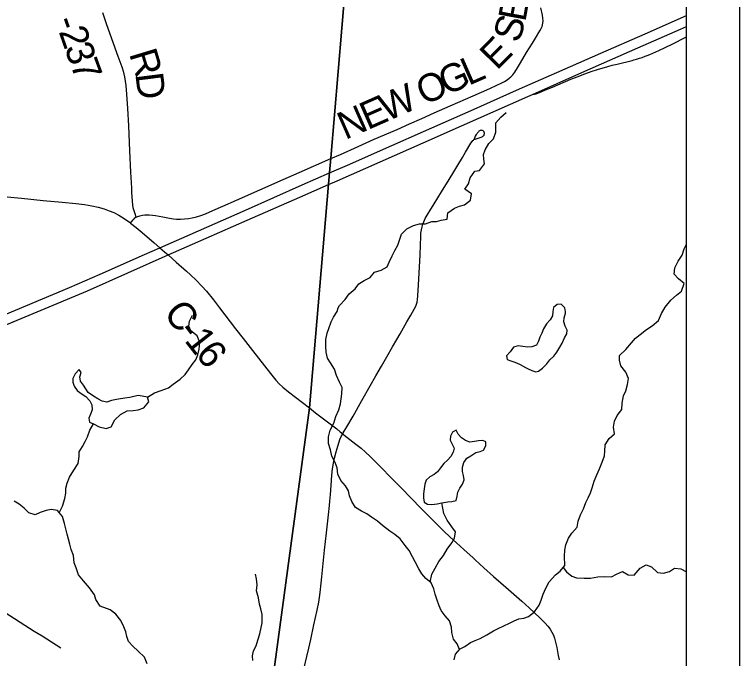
# Model space of a CAD drawing. Extents: x 0 to 34, y 0 to 22.
# Drawn here: x 7.686 to 9.17, y 16.336 to 17.655 of the extents above; entities that cross this region are included whole.
import ezdxf

# ---------------------------------------------------------------- set-up
doc = ezdxf.new("R2010")
doc.units = 0
for name, color, linetype in [('Default', 7, 'Continuous'), ('GM_X_County_Road', 7, 'Continuous'), ('GM_X_County_Road_Text', 7, 'Continuous'), ('GM_X_Interchange_Ramps', 7, 'Continuous'), ('GM_X_Interstate_Location', 7, 'Continuous'), ('GM_X_Interstate_Route', 7, 'Continuous'), ('GM_X_Minor_Lake', 7, 'Continuous'), ('GM_X_Minor_River', 7, 'Continuous'), ('GM_X_Township_Road', 7, 'Continuous'), ('GM_X_Township_Road_Text', 7, 'Continuous'), ('SH_Cut_Line', 7, 'Continuous'), ('SH_Data', 7, 'Continuous')]:
    doc.layers.add(name, color=color, linetype=linetype)

msp = doc.modelspace()

# ---------------------------------------------------------------- linework, layer by layer
at = {"layer": 'Default'}
msp.add_lwpolyline([(3.47, 19.2407), (3.2768, 17.1355), (3.2667, 16.919), (3.1974, 16.1596), (3.1343, 15.4291), (3.1796, 15.4266), (4.2078, 15.3826), (4.2393, 15.3805), (4.819, 15.349), (5.5157, 15.319), (7.9465, 15.1727), (8.1234, 15.1688), (8.137, 15.3372), (8.146, 15.4642), (8.2031, 16.209), (8.2895, 16.85), (8.3286, 17.3076), (8.3307, 17.3314), (8.3334, 17.361), (8.3935, 18.0719)], dxfattribs=at)
msp.add_lwpolyline([(8.4279, 13.6252), (9.0621, 13.6252), (9.0621, 18.0279), (9.0619, 18.0279), (8.9638, 18.036), (8.3935, 18.0719), (8.3334, 17.361), (8.3307, 17.3314), (8.3286, 17.3076), (8.2895, 16.85), (8.2031, 16.209), (8.146, 15.4642), (8.137, 15.3372), (8.1234, 15.1688), (8.3761, 15.1587), (8.4023, 15.1576), (8.4024, 15.1386)], close=True, dxfattribs=at)
at = {"layer": 'GM_X_County_Road'}
for points in [[(8.3337, 17.3604), (8.3531, 17.3688), (8.3893, 17.3851), (8.4223, 17.3996), (8.469, 17.42), (8.4945, 17.4314), (8.5195, 17.4425), (8.5451, 17.4538), (8.5781, 17.4683), (8.6253, 17.4889), (8.6589, 17.5036), (8.6736, 17.5102), (8.6826, 17.5145), (8.6891, 17.518), (8.6948, 17.5216), (8.6988, 17.5245), (8.702, 17.5273), (8.7062, 17.5318), (8.7102, 17.5372), (8.7158, 17.546), (8.7218, 17.5562), (8.7341, 17.5771), (8.7462, 17.5967), (8.7524, 17.6067), (8.7615, 17.6215), (8.7642, 17.6264), (8.7661, 17.6308), (8.7672, 17.6343), (8.7678, 17.6372), (8.7682, 17.642), (8.7679, 17.6475), (8.7667, 17.6541), (8.7637, 17.6688)], [(7.9348, 17.2401), (7.9382, 17.2416), (7.9425, 17.2429), (7.948, 17.2441), (7.9524, 17.2448), (7.9568, 17.245), (7.9612, 17.245), (7.9681, 17.2444), (7.9743, 17.2436), (7.9896, 17.2406), (8.003, 17.2381), (8.0115, 17.2368), (8.0177, 17.2363), (8.0257, 17.2362), (8.0337, 17.2366), (8.0417, 17.2374), (8.0496, 17.2389), (8.0585, 17.2411), (8.0674, 17.2438), (8.0767, 17.2472), (8.0916, 17.2535), (8.112, 17.2625), (8.1405, 17.275), (8.236, 17.317), (8.2683, 17.3316), (8.3337, 17.3604)], [(7.4691, 17.3047), (7.4709, 17.3039), (7.477, 17.3022), (7.4844, 17.3008), (7.4968, 17.2994), (7.5252, 17.2968), (7.5709, 17.2921), (7.5957, 17.2896), (7.6333, 17.2854), (7.7001, 17.2788), (7.7446, 17.2743), (7.783, 17.271), (7.8109, 17.2683), (7.8288, 17.266), (7.844, 17.2633), (7.8567, 17.2605), (7.8692, 17.257), (7.8797, 17.2533), (7.8888, 17.2495), (7.8991, 17.244), (7.9102, 17.2372), (7.9209, 17.2298), (7.9232, 17.2281)], [(7.9232, 17.2281), (7.9255, 17.2309), (7.9288, 17.2349), (7.9305, 17.2369), (7.9323, 17.2386), (7.9348, 17.2401)], [(7.9232, 17.2281), (7.9347, 17.2193), (7.9471, 17.2091), (7.9714, 17.1878), (7.9834, 17.1773), (7.9929, 17.169), (8, 17.1627), (8.0167, 17.148), (8.0377, 17.1296), (8.0461, 17.1222), (8.0577, 17.111), (8.0693, 17.099), (8.0788, 17.0884), (8.0929, 17.0711), (8.1052, 17.0547), (8.1385, 17.0113), (8.1538, 16.9918), (8.1729, 16.9673), (8.2099, 16.9197), (8.2206, 16.9066), (8.2278, 16.8989), (8.235, 16.892), (8.2471, 16.8822), (8.2897, 16.8494)], [(8.2897, 16.8494), (8.3023, 16.8398), (8.3456, 16.8064), (8.3527, 16.8006), (8.3579, 16.7965)], [(8.3579, 16.7965), (8.3603, 16.7947), (8.3848, 16.7754), (8.3954, 16.7668), (8.4044, 16.7592), (8.414, 16.7502), (8.4285, 16.7358), (8.4647, 16.6991), (8.4795, 16.6839), (8.4958, 16.6669), (8.5207, 16.6417), (8.5473, 16.6148), (8.565, 16.5973), (8.5772, 16.5858), (8.5909, 16.5732), (8.606, 16.5593), (8.6248, 16.5422), (8.6294, 16.5381), (8.6468, 16.5222), (8.6668, 16.5045), (8.692, 16.4824), (8.7247, 16.4537), (8.7395, 16.4404), (8.7618, 16.4196), (8.7723, 16.4089), (8.7776, 16.4028), (8.7825, 16.3963), (8.7861, 16.3904), (8.7892, 16.3842), (8.7917, 16.3778), (8.7939, 16.3699), (8.796, 16.3589), (8.799, 16.3425), (8.8012, 16.3335)]]:
    msp.add_lwpolyline(points, dxfattribs=at)
at = {"layer": 'GM_X_Interchange_Ramps'}
msp.add_lwpolyline([(8.7465, 17.4913), (8.7508, 17.4918), (8.7539, 17.4927), (8.7574, 17.494), (8.7639, 17.4966), (8.7734, 17.5007), (8.7872, 17.5062), (8.8247, 17.5226), (8.8381, 17.5279), (8.8537, 17.5338), (8.8668, 17.5383), (8.8798, 17.5427), (8.9007, 17.5489), (8.9099, 17.5513), (8.9199, 17.5538), (8.9503, 17.5612), (8.9543, 17.5622), (8.9597, 17.5637), (8.9653, 17.5655), (8.9712, 17.5675), (8.9769, 17.5697), (8.9813, 17.5713), (8.9868, 17.5736), (9.0051, 17.5818), (9.0328, 17.5943), (9.0608, 17.6088), (9.0621, 17.6095)], dxfattribs=at)
at = {"layer": 'GM_X_Interstate_Route'}
for points in [[(7.6525, 17.0355), (7.7984, 17.0958), (7.8609, 17.1234), (7.952, 17.1634), (7.9834, 17.1773), (8.1588, 17.2547), (8.2747, 17.3062), (8.331, 17.3309), (8.3675, 17.3468), (8.4583, 17.3872), (8.5231, 17.4157), (8.6209, 17.4589), (8.7197, 17.5027), (8.796, 17.5363), (8.8864, 17.5759), (8.9769, 17.6157), (9.0621, 17.6533)], [(8.7465, 17.4913), (8.8475, 17.5363), (8.9625, 17.5867), (9.0494, 17.6251), (9.0621, 17.6308)], [(6.6115, 16.581), (6.7509, 16.6383), (6.8821, 16.6934), (6.9924, 16.7387), (7.2374, 16.8408), (7.3137, 16.8725), (7.3391, 16.883), (7.3498, 16.8874), (7.436, 16.9231), (7.5336, 16.9635), (7.8352, 17.0892), (8, 17.1627), (8.0503, 17.1852), (8.162, 17.2337), (8.2701, 17.2811), (8.3288, 17.307), (8.3462, 17.3149), (8.5226, 17.3923), (8.6009, 17.4272), (8.7368, 17.4871), (8.7465, 17.4913)]]:
    msp.add_lwpolyline(points, dxfattribs=at)
at = {"layer": 'GM_X_Minor_Lake'}
for points in [[(8.8138, 17.0435), (8.8139, 17.0463), (8.8129, 17.0543), (8.8051, 17.062), (8.7971, 17.0611), (8.7895, 17.0555), (8.7881, 17.0468), (8.7876, 17.0381), (8.7825, 17.0299), (8.7751, 17.0217), (8.7692, 17.0115), (8.7653, 17.0029), (8.7613, 16.9946), (8.7589, 16.9863), (8.7545, 16.9781), (8.7454, 16.9748), (8.737, 16.9739), (8.7268, 16.9752), (8.7174, 16.9765), (8.7075, 16.9741), (8.7005, 16.9647), (8.6931, 16.9565), (8.6944, 16.9485), (8.7023, 16.9457), (8.7106, 16.9429), (8.7196, 16.9393), (8.7286, 16.9342), (8.7293, 16.9339)], [(8.7293, 16.9339), (8.7376, 16.9298), (8.7451, 16.9259), (8.7534, 16.9231), (8.7591, 16.9249), (8.7672, 16.9308), (8.7757, 16.9401), (8.7823, 16.9483), (8.7904, 16.9557), (8.7963, 16.964), (8.8022, 16.9741), (8.8073, 16.9823), (8.8117, 16.9929), (8.8168, 17.0011), (8.8177, 17.0087), (8.8133, 17.0167), (8.8104, 17.0255), (8.8114, 17.0342), (8.8138, 17.0435)], [(7.9073, 16.8687), (7.9029, 16.8678), (7.8942, 16.8669), (7.8843, 16.8644), (7.8744, 16.8612), (7.8653, 16.8636), (7.8563, 16.8684), (7.8473, 16.8735), (7.8365, 16.8809), (7.8317, 16.8886), (7.8266, 16.8963), (7.8211, 16.9043), (7.8197, 16.9131), (7.8218, 16.9222), (7.8181, 16.9279), (7.8096, 16.919), (7.8049, 16.91), (7.8051, 16.902), (7.8076, 16.8944), (7.8142, 16.8851), (7.8224, 16.8793), (7.8318, 16.8727), (7.8396, 16.8638), (7.8443, 16.8557), (7.8445, 16.8458), (7.8413, 16.8368), (7.8381, 16.8285), (7.8394, 16.8201), (7.8477, 16.8169)], [(7.8477, 16.8169), (7.8593, 16.8106), (7.8736, 16.8077), (7.8835, 16.8109), (7.8914, 16.8248), (7.903, 16.836), (7.9164, 16.8433), (7.9289, 16.8442), (7.9392, 16.8455), (7.9506, 16.8498), (7.9604, 16.8621), (7.9583, 16.8717)], [(7.9583, 16.8717), (7.9394, 16.8747), (7.9299, 16.873), (7.9215, 16.8709), (7.9113, 16.8696), (7.9073, 16.8687)], [(8.6092, 16.7425), (8.6123, 16.7468), (8.6199, 16.7516), (8.6303, 16.7582), (8.6394, 16.7603), (8.6459, 16.7632), (8.651, 16.7718), (8.6512, 16.7798), (8.6445, 16.783), (8.6361, 16.782), (8.6277, 16.7807), (8.6182, 16.7797), (8.6092, 16.7825), (8.6014, 16.7884), (8.5943, 16.7957), (8.5899, 16.8038), (8.5823, 16.8001), (8.5783, 16.7915), (8.5782, 16.7832), (8.5818, 16.7751), (8.5858, 16.7671), (8.5841, 16.7591), (8.5794, 16.7501), (8.5724, 16.7427), (8.5651, 16.7356), (8.5581, 16.7266), (8.5518, 16.7184), (8.5449, 16.7129)], [(8.5449, 16.7129), (8.5361, 16.7085), (8.5288, 16.7018), (8.5263, 16.6931), (8.5246, 16.6837), (8.5233, 16.6738), (8.5231, 16.6655), (8.5244, 16.6567), (8.5315, 16.6521), (8.5406, 16.6519), (8.5509, 16.6532), (8.5611, 16.6553), (8.5733, 16.6569), (8.5816, 16.6579), (8.59, 16.6596), (8.5925, 16.6687), (8.5938, 16.677), (8.5974, 16.6853), (8.6028, 16.6935), (8.6068, 16.7022), (8.6051, 16.7113), (8.603, 16.7193), (8.6028, 16.728), (8.6056, 16.7375), (8.6092, 16.7425)]]:
    msp.add_lwpolyline(points, dxfattribs=at)
at = {"layer": 'GM_X_Minor_River'}
for points in [[(8.3487, 17.0548), (8.3511, 17.0591), (8.3627, 17.0718), (8.3713, 17.0834), (8.3832, 17.0934), (8.3907, 17.1039), (8.4014, 17.1102), (8.4141, 17.1168), (8.423, 17.1276), (8.4364, 17.1319), (8.4487, 17.1385), (8.4527, 17.1483), (8.459, 17.161), (8.4645, 17.1719), (8.4708, 17.1828), (8.4749, 17.1949), (8.4781, 17.2051), (8.489, 17.2163), (8.5028, 17.2228), (8.515, 17.2264), (8.5275, 17.2265), (8.5401, 17.2312), (8.5496, 17.2314), (8.5592, 17.2339), (8.5714, 17.2363), (8.5731, 17.2488), (8.587, 17.2584), (8.5973, 17.2627), (8.6069, 17.2656), (8.6196, 17.2748), (8.6214, 17.2881), (8.6079, 17.2974), (8.6157, 17.3083), (8.6186, 17.3208), (8.6284, 17.3346), (8.6379, 17.336), (8.648, 17.3494), (8.6471, 17.3589), (8.6458, 17.3685), (8.6494, 17.3783), (8.6568, 17.391), (8.6665, 17.4007), (8.6713, 17.4143), (8.6712, 17.4238), (8.6713, 17.4333), (8.6814, 17.4448), (8.6923, 17.4545)], [(9.0106, 17.043), (9.0184, 17.0561), (9.0301, 17.0703), (9.0417, 17.0807), (9.0518, 17.0889), (9.057, 17.104), (9.0454, 17.1137), (9.0369, 17.1237), (9.0379, 17.1366), (9.045, 17.1498), (9.0528, 17.1625), (9.0573, 17.1753), (9.0621, 17.1846)], [(8.5967, 16.3547), (8.5923, 16.3663), (8.585, 16.376), (8.5811, 16.3897), (8.5809, 16.4003), (8.5766, 16.4133), (8.5678, 16.4237), (8.5593, 16.4345), (8.5553, 16.4441), (8.5506, 16.4578), (8.5474, 16.4681), (8.5446, 16.4788), (8.5388, 16.4911), (8.5277, 16.5004), (8.5199, 16.51), (8.5137, 16.52), (8.506, 16.5342), (8.5005, 16.5446), (8.494, 16.5572), (8.4858, 16.5676), (8.4755, 16.5811), (8.4647, 16.5904), (8.4543, 16.5974), (8.439, 16.6087), (8.4289, 16.6173), (8.417, 16.6259), (8.4072, 16.6325), (8.3964, 16.6384), (8.384, 16.6455), (8.3763, 16.6578), (8.372, 16.6692), (8.3696, 16.6799), (8.3633, 16.6899), (8.3541, 16.7007), (8.3479, 16.7141), (8.3463, 16.7267), (8.3423, 16.7377), (8.3354, 16.7508), (8.3326, 16.7634), (8.3284, 16.7767), (8.3286, 16.79), (8.3323, 16.8039), (8.3395, 16.8186), (8.3439, 16.8322), (8.3499, 16.8453), (8.3535, 16.8578), (8.3562, 16.8782), (8.3565, 16.8911), (8.351, 16.9022), (8.3449, 16.916), (8.3413, 16.929), (8.3325, 16.9417), (8.3263, 16.9513), (8.3239, 16.9638), (8.323, 16.9752), (8.3233, 16.9896), (8.3258, 17.0025), (8.3294, 17.0123), (8.3342, 17.0258), (8.339, 17.0356), (8.3464, 17.0472), (8.3487, 17.0548)], [(7.7774, 16.6349), (7.7836, 16.6486), (7.7888, 16.6637), (7.7906, 16.6747), (7.7904, 16.6849), (7.7933, 16.6955), (7.7981, 16.7075), (7.8071, 16.7222), (7.8157, 16.736), (7.8179, 16.75), (7.8181, 16.7599), (7.8248, 16.7704), (7.8303, 16.7805), (7.835, 16.7906), (7.8402, 16.8042), (7.8477, 16.8169), (7.8593, 16.8106), (7.8736, 16.8077), (7.8835, 16.8109), (7.8914, 16.8248), (7.903, 16.836), (7.9164, 16.8433), (7.9289, 16.8442), (7.9392, 16.8455), (7.9506, 16.8498), (7.9604, 16.8621), (7.9583, 16.8717), (7.9721, 16.8801), (7.9862, 16.8855), (8.0007, 16.8906), (8.0107, 16.8983), (8.0246, 16.9083), (8.0354, 16.9179), (8.042, 16.9277), (8.0498, 16.9385), (8.0572, 16.9482), (8.0612, 16.958), (8.0641, 16.9701), (8.0652, 16.9837), (8.0597, 16.9971), (8.0467, 17.0076), (8.0427, 17.0172), (8.0441, 17.027), (8.0504, 17.0394)], [(8.8127, 16.5266), (8.8123, 16.5456), (8.8126, 16.5585), (8.8147, 16.5691), (8.8203, 16.5826), (8.8273, 16.5927), (8.8382, 16.6054), (8.84, 16.6179), (8.8448, 16.6307), (8.8511, 16.6427), (8.8555, 16.6555), (8.8606, 16.6653), (8.865, 16.6754), (8.8686, 16.686), (8.8727, 16.6992), (8.8783, 16.7127), (8.8838, 16.7248), (8.8894, 16.7383), (8.8938, 16.7515), (8.8948, 16.7613), (8.8954, 16.7738), (8.9037, 16.7866), (8.9141, 16.7966), (8.9125, 16.8099), (8.9142, 16.8224), (8.9202, 16.8341), (8.9291, 16.8464), (8.9298, 16.8593), (8.9331, 16.8744), (8.9375, 16.8842), (8.9412, 16.8977), (8.9433, 16.9095), (8.9375, 16.9229), (8.9272, 16.936), (8.9244, 16.9474), (8.9246, 16.9569), (8.9373, 16.9691), (8.9493, 16.9826), (8.9571, 16.9923), (8.9668, 17), (8.9802, 17.01), (8.9914, 17.0174), (9.0045, 17.0285), (9.0106, 17.043)], [(7.9573, 16.3254), (7.9519, 16.3388), (7.9389, 16.3516), (7.9277, 16.3616), (7.9192, 16.3713), (7.9156, 16.3812), (7.9136, 16.3908), (7.9092, 16.4015), (7.9031, 16.4141), (7.8931, 16.4272), (7.8812, 16.4358), (7.8609, 16.4438), (7.8524, 16.4572), (7.8492, 16.4668), (7.8389, 16.481), (7.8267, 16.4957), (7.8167, 16.508), (7.8121, 16.5221), (7.8081, 16.5321), (7.8062, 16.5473), (7.8015, 16.5599), (7.7987, 16.5706), (7.7962, 16.5805), (7.7938, 16.5908), (7.791, 16.6018), (7.7878, 16.6129), (7.7836, 16.627), (7.774, 16.6393), (7.7604, 16.6415), (7.7508, 16.6394), (7.7379, 16.6351), (7.7276, 16.6308), (7.7148, 16.6344), (7.7051, 16.6441), (7.6954, 16.6527), (7.6846, 16.6589)], [(8.5371, 16.4925), (8.5403, 16.5089), (8.5474, 16.5216), (8.5549, 16.5351), (8.5642, 16.5475), (8.5717, 16.5602), (8.581, 16.5733), (8.5869, 16.5831), (8.5887, 16.5959), (8.5813, 16.6059), (8.5714, 16.6194), (8.5652, 16.6336), (8.5611, 16.6553)], [(8.586, 16.3338), (8.5889, 16.3455), (8.5982, 16.3564), (8.6081, 16.3611), (8.6197, 16.3692), (8.6292, 16.3732), (8.6395, 16.3775), (8.653, 16.3849), (8.6664, 16.3929), (8.6759, 16.3977), (8.6878, 16.4035), (8.6993, 16.409), (8.7088, 16.4133), (8.7188, 16.4173), (8.7287, 16.419), (8.7382, 16.4226), (8.7505, 16.4322), (8.7603, 16.4457), (8.7643, 16.4555), (8.7683, 16.4683), (8.7739, 16.4803), (8.7806, 16.4935), (8.7937, 16.5076), (8.8034, 16.515), (8.8127, 16.5266)], [(8.8095, 16.5226), (8.8158, 16.5137), (8.827, 16.5047), (8.8368, 16.5015), (8.852, 16.5008), (8.8656, 16.5009), (8.8804, 16.5033), (8.8948, 16.5045), (8.9081, 16.5039), (8.9184, 16.5094), (8.9307, 16.5148), (8.9426, 16.5077), (8.9547, 16.5071), (8.9672, 16.5213), (8.979, 16.5283), (8.9899, 16.5239), (9.0022, 16.5126), (9.0147, 16.5112), (9.0269, 16.5148), (9.0372, 16.5214), (9.0505, 16.52), (9.0621, 16.5138)], [(8.1738, 16.3321), (8.1728, 16.3416), (8.1753, 16.3522), (8.1805, 16.3623), (8.1841, 16.3736), (8.1878, 16.3869), (8.1928, 16.4095), (8.1927, 16.4262), (8.1903, 16.438), (8.1875, 16.4479), (8.1851, 16.4609), (8.1812, 16.4746), (8.1823, 16.4875), (8.1814, 16.4997), (8.1789, 16.5092)]]:
    msp.add_lwpolyline(points, dxfattribs=at)
at = {"layer": 'GM_X_Township_Road'}
for points in [[(7.9348, 17.2401), (7.9324, 17.2472), (7.9304, 17.2531), (7.9288, 17.2596), (7.9278, 17.2657), (7.927, 17.273), (7.9262, 17.2904), (7.9258, 17.2997), (7.9242, 17.332), (7.922, 17.3761), (7.9197, 17.427), (7.9176, 17.463), (7.9156, 17.4921), (7.9142, 17.5101), (7.9131, 17.5188), (7.9115, 17.5274), (7.9092, 17.5365), (7.9058, 17.5472), (7.8978, 17.5694), (7.8748, 17.6338), (7.8663, 17.6584)], [(8.3579, 16.7965), (8.359, 16.7986), (8.3662, 16.8109), (8.379, 16.8329), (8.3969, 16.8649), (8.4141, 16.8951), (8.4259, 16.9155), (8.437, 16.9349), (8.448, 16.9544), (8.4599, 16.9748), (8.4687, 16.9898), (8.4757, 17.0015), (8.4893, 17.0259), (8.497, 17.0394), (8.5042, 17.0517), (8.5073, 17.0577), (8.5089, 17.0617), (8.5102, 17.0664), (8.5112, 17.0718), (8.5119, 17.0791), (8.5132, 17.1014), (8.5149, 17.1381), (8.5161, 17.1629), (8.5176, 17.2014), (8.518, 17.2076), (8.519, 17.2144), (8.5203, 17.2206), (8.5218, 17.226), (8.5236, 17.2307), (8.5269, 17.2375), (8.5309, 17.2446), (8.5384, 17.2568), (8.5398, 17.2588), (8.5449, 17.2674), (8.5602, 17.2922), (8.5755, 17.3171), (8.5854, 17.3328), (8.5937, 17.3467), (8.6029, 17.3622), (8.6067, 17.3686), (8.6096, 17.3733), (8.6202, 17.3917), (8.6227, 17.3954), (8.6245, 17.3973), (8.6255, 17.3981), (8.6266, 17.3989), (8.628, 17.3996), (8.629, 17.4001), (8.6373, 17.4027), (8.6414, 17.404), (8.6435, 17.405), (8.645, 17.4059), (8.646, 17.4067), (8.6468, 17.4075), (8.6472, 17.4083), (8.6476, 17.4091), (8.6478, 17.4099), (8.648, 17.4111), (8.6481, 17.4122), (8.648, 17.4131), (8.6478, 17.4139), (8.6474, 17.4147), (8.6468, 17.4155), (8.6462, 17.4163), (8.6453, 17.4171), (8.6444, 17.4176), (8.6434, 17.4179), (8.6423, 17.4181), (8.6407, 17.418), (8.6391, 17.4175), (8.6377, 17.4167), (8.6368, 17.416), (8.6359, 17.4152), (8.6349, 17.4141), (8.6339, 17.4129), (8.633, 17.4118), (8.6314, 17.4094), (8.6291, 17.4058), (8.6282, 17.4041), (8.6275, 17.4021), (8.6267, 17.3997)], [(8.2787, 16.3175), (8.2846, 16.3405), (8.2887, 16.3572), (8.2924, 16.3754), (8.2989, 16.4052), (8.3056, 16.4355), (8.3089, 16.4519), (8.3105, 16.4611), (8.3118, 16.4715), (8.3137, 16.4907), (8.315, 16.5037), (8.3165, 16.5172), (8.3208, 16.558), (8.3247, 16.5938), (8.3286, 16.6303), (8.3307, 16.65), (8.3317, 16.6586), (8.3329, 16.6722), (8.3341, 16.6907), (8.3356, 16.7118), (8.337, 16.7248), (8.3388, 16.7365), (8.3407, 16.7463), (8.3443, 16.7596), (8.3462, 16.7662), (8.3521, 16.7846), (8.3547, 16.7909), (8.3579, 16.7965)], [(7.6213, 16.4593), (7.6456, 16.4438), (7.6644, 16.4317), (7.6974, 16.4105), (7.7257, 16.3925), (7.7422, 16.3825), (7.7803, 16.358)]]:
    msp.add_lwpolyline(points, dxfattribs=at)
at = {"layer": 'SH_Cut_Line'}
msp.add_lwpolyline([(2.9696, 13.6252), (9.0621, 13.6252), (9.0621, 20.4252), (3.5682, 20.4252), (3.5424, 20.1754), (3.5231, 19.8516), (3.5169, 19.7823), (3.5125, 19.7343), (3.5092, 19.6961), (3.5066, 19.6647), (3.4966, 19.5464), (3.4903, 19.4759), (3.4748, 19.2963), (3.47, 19.2407), (3.2768, 17.1355), (3.2667, 16.919), (3.1974, 16.1596), (3.1343, 15.4291), (3.0617, 14.6751), (3.0457, 14.4958), (3.0429, 14.4692)], close=True, dxfattribs=at)
at = {"layer": 'SH_Data'}
msp.add_line((9.1704, 20.5628), (9.1704, 13.5628), dxfattribs=at)

# ---------------------------------------------------------------- texts
at = {"layer": 'GM_X_County_Road_Text'}
for s, rotation, p in [('B', 79.66, (8.7317, 17.6387)), ('S', 73.0449, (8.7188, 17.5951)), ('E', 45.2871, (8.6736, 17.5393)), ('L', 23.7478, (8.6156, 17.509)), ('G', 23.7317, (8.5698, 17.4889)), ('O', 23.7357, (8.5241, 17.4688)), ('W', 23.7299, (8.4478, 17.4353)), ('E', 23.7293, (8.4089, 17.4182)), ('N', 23.731, (8.3631, 17.398)), ('C', 307.7692, (7.9891, 17.043)), ('-', 307.8203, (8.0177, 17.006)), ('1', 308.0429, (8.0322, 16.9874)), ('6', 309.0693, (8.0545, 16.959))]:
    msp.add_text(s, height=0.0568, rotation=rotation, dxfattribs=at).set_placement(p)
at = {"layer": 'GM_X_Interstate_Location'}
for s in ['.', '-', ',']:
    msp.add_text(s, height=0.000189, dxfattribs=at).set_placement((8.955, 17.5838))
msp.add_text('71', height=0.000189, rotation=0, dxfattribs=at).set_placement((8.9163, 17.5445))
at = {"layer": 'GM_X_Township_Road_Text'}
for s, rotation, p in [('-', 289.2268, (7.768, 17.6425)), ('2', 289.2641, (7.7757, 17.6204)), ('3', 289.4272, (7.7873, 17.5872)), ('R', 286.8772, (7.9199, 17.5751)), ('7', 290.0743, (7.7992, 17.5535)), ('D', 277.2543, (7.9329, 17.5329))]:
    msp.add_text(s, height=0.0568, rotation=rotation, dxfattribs=at).set_placement(p)

doc.saveas('drawing.dxf')
